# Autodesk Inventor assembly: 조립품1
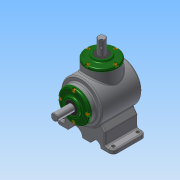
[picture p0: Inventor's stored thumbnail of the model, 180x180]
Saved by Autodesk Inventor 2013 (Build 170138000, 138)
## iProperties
Created: 2018-08
Part Number: 조립품1
Document SubType Name: Assembly
Designer: Administrator
Author: Administrator
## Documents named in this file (14)
- C:\Users\Administrator\Desktop\480808V1021\조립품1.iam
- C:\Users\Administrator\Desktop\480808V1021\본체.ipt
- C:\Users\Administrator\Desktop\480808V1021\메인 축.ipt
- 메인 축.ipt
- C:\Users\Administrator\Desktop\480808V1021\키 5x5.ipt
- C:\Users\Administrator\Desktop\480808V1021\메인 베벨기어.ipt
- C:\Users\Administrator\Desktop\480808V1021\베어링 6203.ipt
- C:\Users\Administrator\Desktop\480808V1021\커버.ipt
- C:\Users\Administrator\Desktop\480808V1021\오일실 17 32 8.ipt
- C:\Users\Administrator\Desktop\480808V1021\볼트 M4.ipt
- C:\Users\Administrator\Desktop\480808V1021\서브 축.ipt
- 서브 축.ipt
- C:\Users\Administrator\Desktop\480808V1021\키 4x4.ipt
- C:\Users\Administrator\Desktop\480808V1021\서브 베벨기어.ipt
